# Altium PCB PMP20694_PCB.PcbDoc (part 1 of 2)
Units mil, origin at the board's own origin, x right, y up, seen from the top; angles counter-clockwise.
Board outline 7086.61 x 2677.17 mil, 2 copper layers (Top Layer, Bottom Layer), stack 62 mil thick; 190 components, 99 nets, 453 pads, 121 vias.
Unrouted connection lines stored in the file: 1.
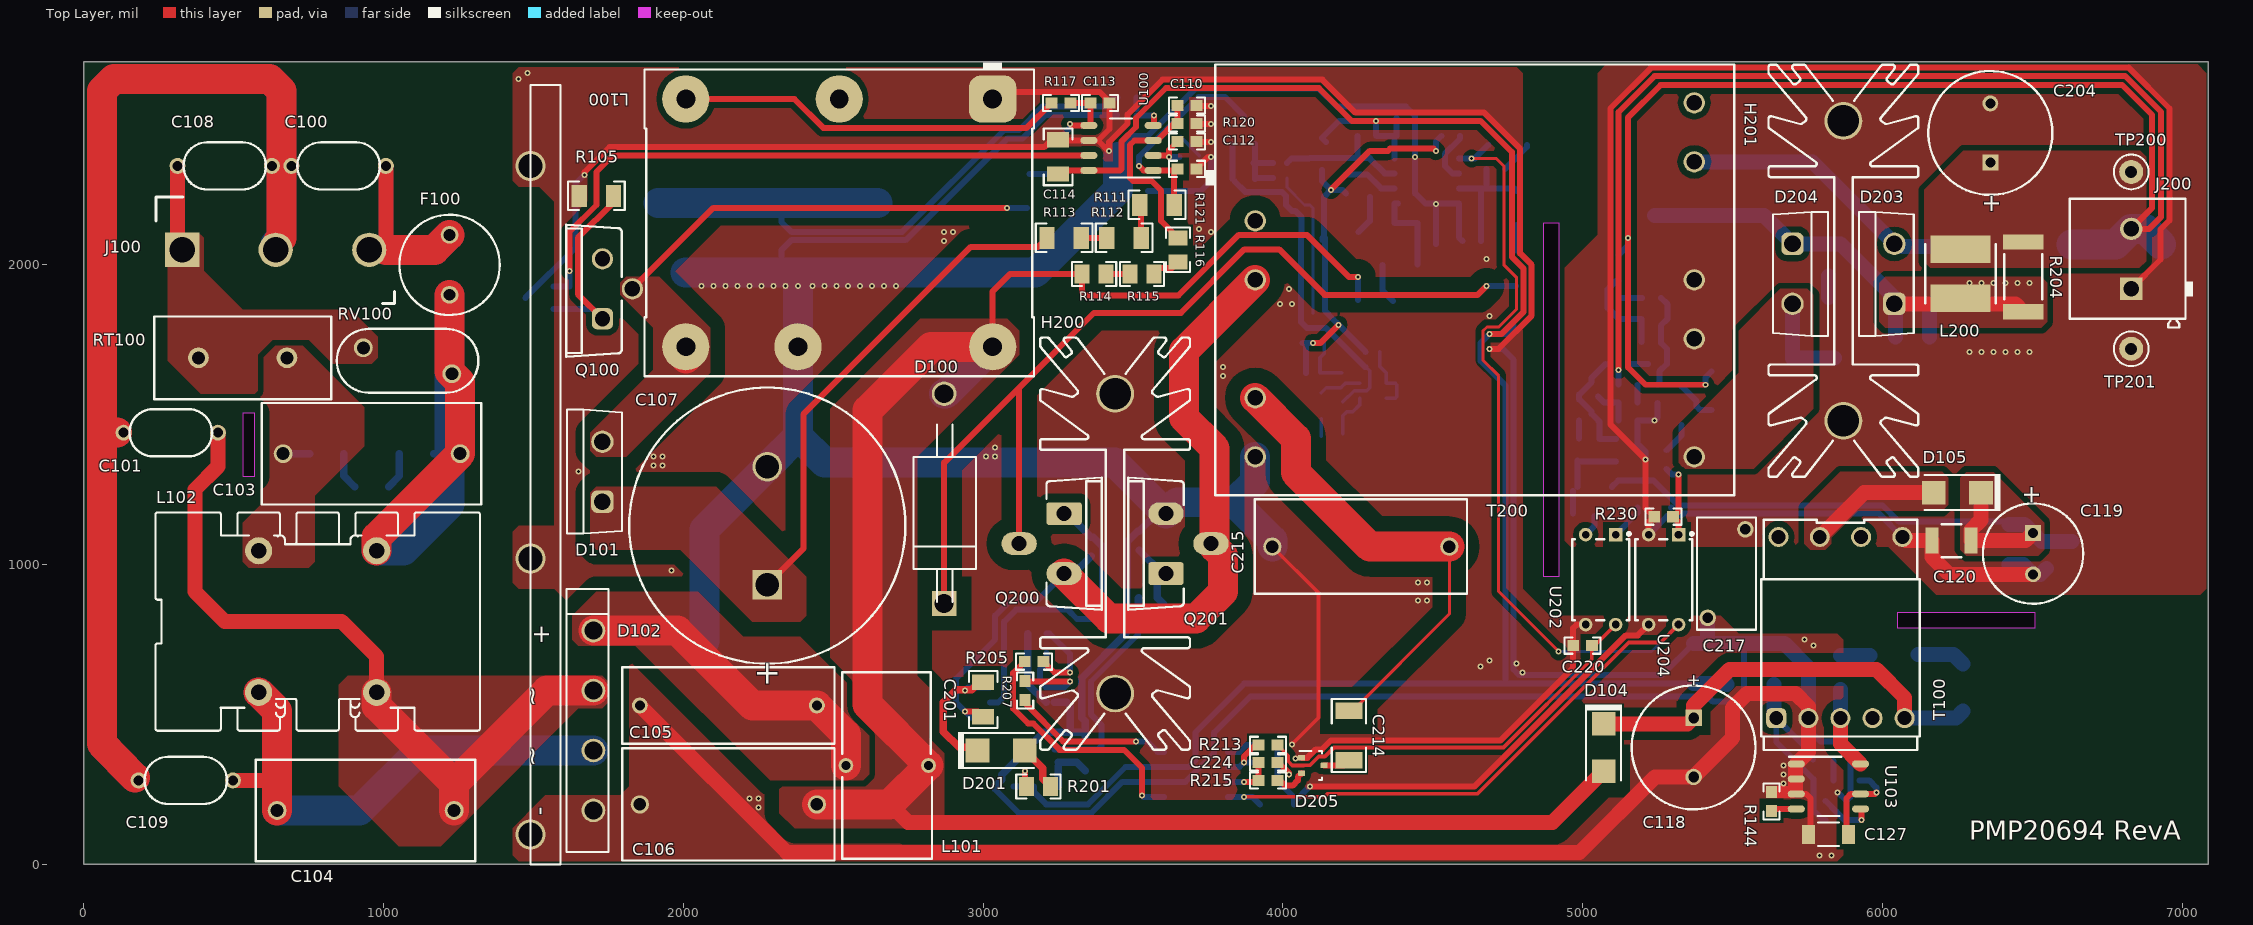
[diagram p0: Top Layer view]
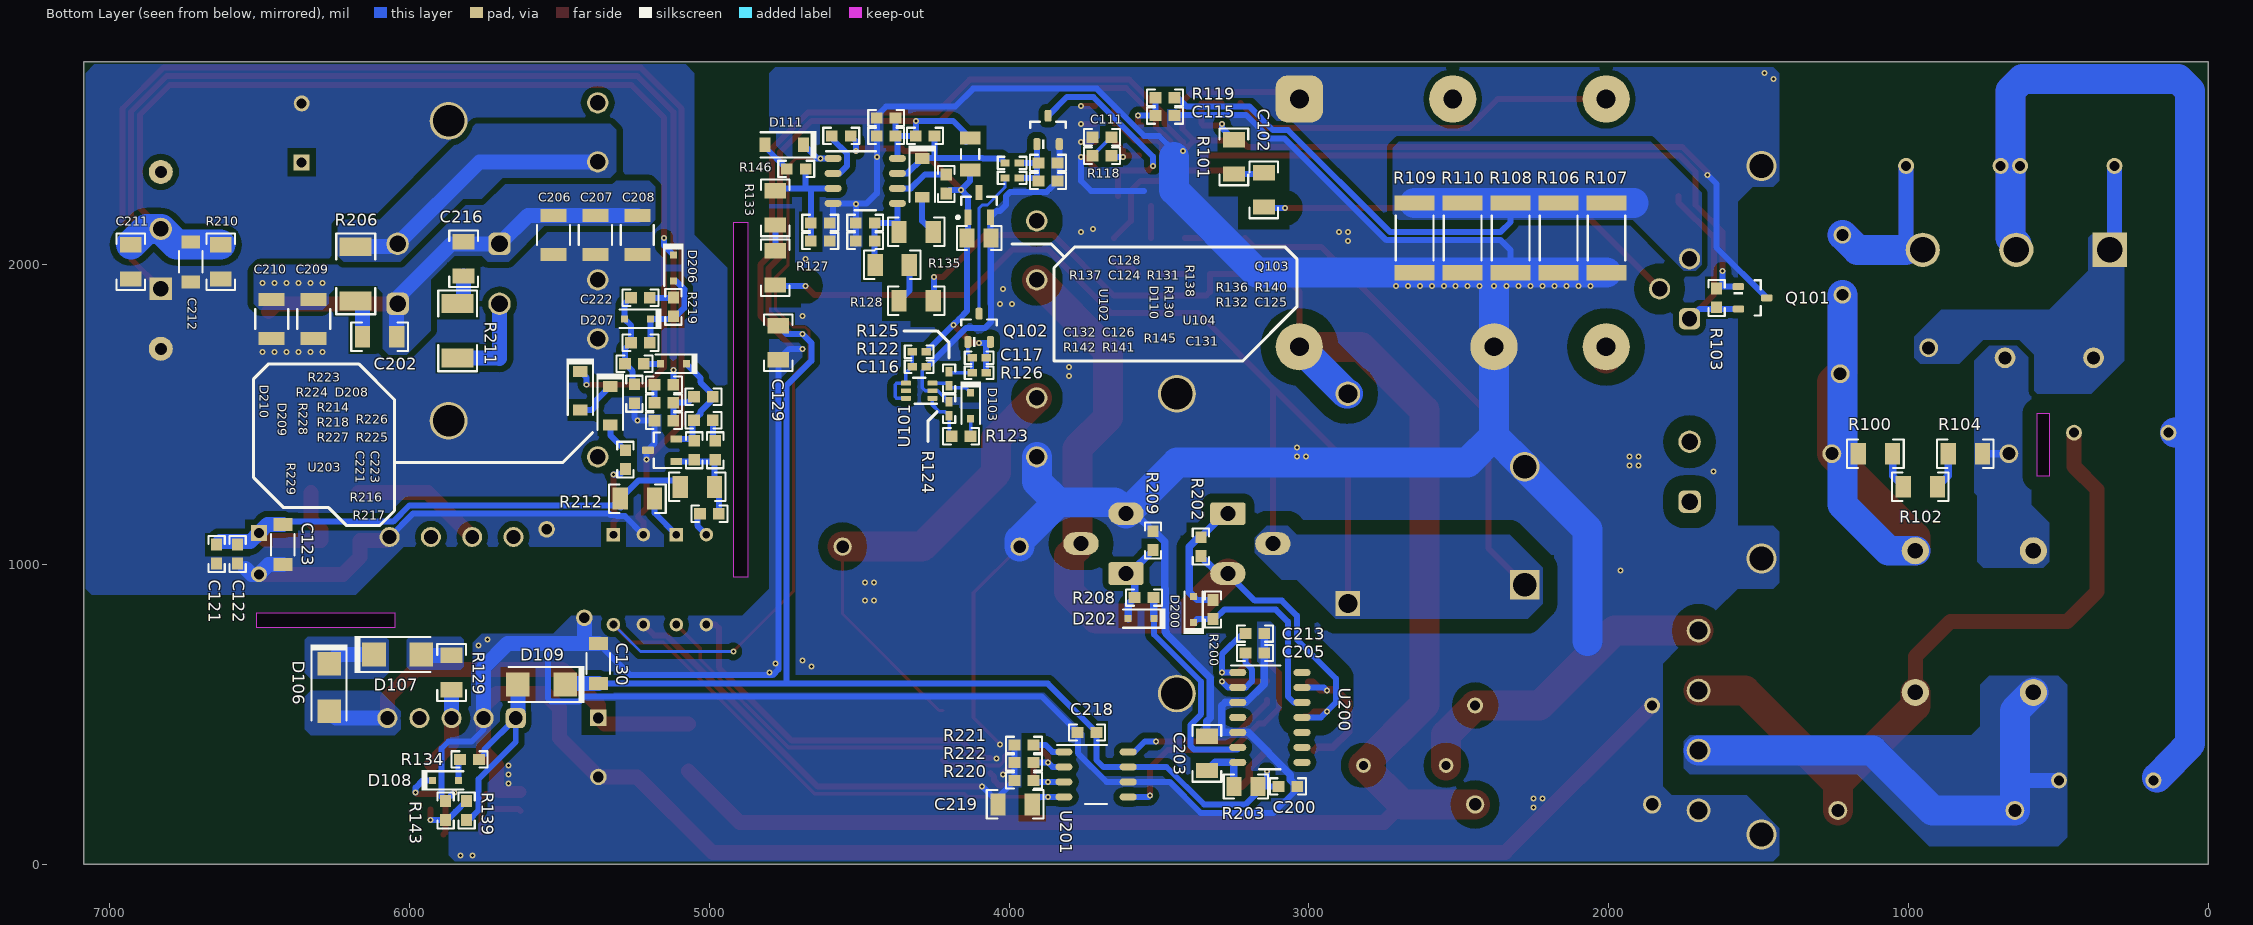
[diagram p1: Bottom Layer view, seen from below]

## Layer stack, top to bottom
Top Solder: solder mask 0.4, Solder Resist, Dk 3.5
Top Layer: signal copper 1.4
Dielectric1: core 59.2, FR-4, Dk 4.8
Bottom Layer: signal copper 1.4
Bottom Solder: solder mask 0.4, Solder Resist, Dk 3.5

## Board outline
0,0 7086.61,0 7086.61,2677.17 0,2677.17
cut-out: 530,1295 570,1295 570,1505 530,1505
cut-out: 6050,790 6510,790 6510,840 6050,840
cut-out: 4870,960 4870,2140 4920,2140 4920,960

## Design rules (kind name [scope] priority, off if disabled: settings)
AcuteAngle [All] p1: minimum=4.50000000000000E+0001 checktracksonly=FALSE
AssemblyTestPointUsage [All] p1: valid=2
Clearance Clearance_1 [InNetClass('HV') vs Not InNetClass('HV') and not InNetClass('MV')] p1: gap=50
Clearance Clearance_2 [InNetClass('MV') vs Not InNetClass('MV')] p2: gap=30
Clearance Clearance_Keepouts [((IsTrack Or IsArc) And Not InPoly) And IsFree and IsKeepOut vs ((IsTrack Or IsArc) And Not InPoly) And IsFree and IsKeepOut] p3: gap=0
Clearance Clearance_BoardEdge_MountingHoles [OnCopper and InComponentClass('Mounting Holes') vs IsKeepOut] p4: gap=40
Clearance Clearance_BoardEdge_Poly [OnCopper and InPoly vs IsKeepOut] p5: gap=25
Clearance Clearance_BoardEdge [OnCopper and Not InComponentClass('Logo') and not InComponentClass('FiducialMark') and not InRegion(1000,500,4000,800) and Not IsKeepout vs IsKeepOut] p6: gap=75
Clearance Clearance_Poly [InPolygon] p7: gap=20
Clearance [All] p8: gap=7.87
ComponentClearance ComponentClearance_MountingHoles_FiducialMarks [InComponentClass('Mounting Holes') vs InComponentClass('FiducialMark')] p1: gap=20 collisioncheckmode=3 verticalgap=10 showdistances=FALSE
ComponentClearance ComponentClearance_Shunt [InComponentClass('Header') vs InComponentClass('Shunt')] p2: gap=0 collisioncheckmode=3 verticalgap=0 showdistances=FALSE
ComponentClearance ComponentClearance_Logo [InComponentClass('Logo')] p3: gap=5 collisioncheckmode=3 verticalgap=10 showdistances=FALSE
ComponentClearance ComponentClearance_ScrewToNut [(HasFootprint('NY PMS 440 0025 PH')) vs (HasFootprint('Keystone_1902C'))] p4: gap=20 collisioncheckmode=3 verticalgap=100000 showdistances=FALSE
ComponentClearance ComponentClearance_MountingHoles [InComponentClass('Mounting Holes')] p5: gap=20 collisioncheckmode=3 verticalgap=10 showdistances=FALSE
ComponentClearance ComponentClearance_SmallPassives [HasFootprint('0201*') or HasFootprint('0402*') or HasFootprint('0508') or HasFootprint('0603*') or HasFootprint('0612') or HasFootprint('0805*') or HasFootprint('0815*') or HasFootprint('0830*') or HasFootprint('1206*') or HasFootprint('1210*') or HasFootprint('1808*') or HasFootprint('1812*') or HasFootprint('1825*') or HasFootprint('2010*') or HasFootprint('2220*') or HasFootprint('2225*') or HasFootprint('2512*') or HasFootprint('2728*') or HasFootprint('3518*') vs HasFootprint('0201*') or HasFootprint('0402*') or HasFootprint('0508') or HasFootprint('0603*') or HasFootprint('0612') or HasFootprint('0805*') or HasFootprint('0815*') or HasFootprint('0830*') or HasFootprint('1206*') or HasFootprint('1210*') or HasFootprint('1808*') or HasFootprint('1812*') or HasFootprint('1825*') or HasFootprint('2010*') or HasFootprint('2220*') or HasFootprint('2225*') or HasFootprint('2512*') or HasFootprint('2728*') or HasFootprint('3518*')] p6: gap=20 collisioncheckmode=3 verticalgap=20 showdistances=FALSE
ComponentClearance ComponentClearance_THtoSMT [IsThruComponent vs IsSMTComponent] p7: gap=10 collisioncheckmode=3 verticalgap=10 showdistances=FALSE
ComponentClearance ComponentClearance_THtoTH [IsThruComponent vs IsThruComponent] p8: gap=10 collisioncheckmode=3 verticalgap=10 showdistances=FALSE
ComponentClearance [All] p9: gap=10 collisioncheckmode=3 verticalgap=10 showdistances=FALSE
DiffPairsRouting [All] p1: maxlimit=100 minlimit=10 mostfreqgap=10 toplayer_minwidth=15 toplayer_maxwidth=15 toplayer_prefwidth=15 bottomlayer_minwidth=15 bottomlayer_maxwidth=15 bottomlayer_prefwidth=15 maxuncoupledlength=1000
FabricationTestPointUsage TestPointUsage [All] p1: valid=2 allowmultiple=FALSE
FabricationTestpoint Testpoint [All] p1: side=3 testpointundercomponent=TRUE minsize=40 maxsize=100 preferedsize=60 minholesize=0 maxholesize=40 preferedholesize=32 testpointgrid=1 allowsidetop=TRUE allowsidebottom=TRUE usegrid=TRUE gridtolerance=0.01
FanoutControl Fanout_LCC [IsLCC] p1: bgadir=Out bgaviamode=Centered fanoutstyle=Auto fanoutdirection=Alternating viagrid=1 // Fanout_LCC (Default Rule)
FanoutControl Fanout_BGA [IsBGA] p2: bgadir=Out bgaviamode=Centered fanoutstyle=Auto fanoutdirection=Alternating viagrid=1 // Fanout_BGA (Default Rule)
FanoutControl Fanout_Default [All] p4: bgadir=Out bgaviamode=Centered fanoutstyle=Auto fanoutdirection=Alternating viagrid=1 // Fanout_Default (Default Rule)
FanoutControl Fanout_Small [(CompPinCount < 5)] p5: bgadir=Out bgaviamode=Centered fanoutstyle=Auto fanoutdirection=OutThenIn viagrid=1 // Fanout_Small (Default Rule)
Height [All] p1: minheight=0 maxheight=3000 prefheight=500
HoleSize [All] p1: absolutevalues=TRUE maxlimit=251 minlimit=7 maxpercent=80.000 minpercent=20.000
MinimumAnnularRing MinimumAnnularRing_ThermalPadVias [IsVia and InAnyComponent] p1: minimumring=5.91
MinimumAnnularRing [All] p2: minimumring=4.9
MinimumSolderMaskSliver MinimumSolderMaskSliver_Logo [InComponentClass('Logo') vs InComponentClass('Logo')] p1: minsoldermaskwidth=0.7
MinimumSolderMaskSliver [All] p2: minsoldermaskwidth=2
PlaneConnect [All] p1: planeconnectstyle=Relief reliefexpansion=10 reliefentries=4 reliefconductorwidth=10 reliefairgap=10
PolygonConnect [All] p1: connectstyle=Direct reliefconductorwidth=10 reliefentries=4 polygonreliefangle="90 Angle" airgapwidth=10
PolygonConnect PolygonConnect_10 [All vs IsNamedPolygon('C108_1') Or  IsNamedPolygon('C103_2')] p2: connectstyle=Direct reliefconductorwidth=10 reliefentries=4 polygonreliefangle="90 Angle" airgapwidth=10
PolygonConnect PolygonConnect_9 [All vs IsNamedPolygon('C11_1') Or  IsNamedPolygon('Vin') Or  IsNamedPolygon('Vin') Or  IsNamedPolygon('5V') Or  IsNamedPolygon('D6_2') Or  IsNamedPolygon('Q3_3') Or  IsNamedPolygon('GND2') Or  IsNamedPolygon('GND2') Or  IsNamedPolygon('GND') Or  IsNamedPolygon('Q3_4') Or  IsNamedPolygon('12V5') Or  IsNamedPolygon('GND') Or  IsNamedPolygon('12V5') Or  IsNamedPolygon('D3_1')] p3: connectstyle=Direct reliefconductorwidth=10 reliefentries=4 polygonreliefangle="90 Angle" airgapwidth=10
PolygonConnect PolygonConnect_8 [All vs IsNamedPolygon('C11_1') Or  IsNamedPolygon('Vin') Or  IsNamedPolygon('12V5') Or  IsNamedPolygon('Q3_3') Or  IsNamedPolygon('GND2') Or  IsNamedPolygon('GND2') Or  IsNamedPolygon('5V') Or  IsNamedPolygon('Q3_4') Or  IsNamedPolygon('12V5')] p4: connectstyle=Direct reliefconductorwidth=10 reliefentries=4 polygonreliefangle="90 Angle" airgapwidth=10
PolygonConnect PolygonConnect_7 [All vs IsNamedPolygon('GND2') Or  IsNamedPolygon('GND2') Or  IsNamedPolygon('5V') Or  IsNamedPolygon('12V5') Or  IsNamedPolygon('12V5') Or  IsNamedPolygon('C11_1')] p5: connectstyle=Direct reliefconductorwidth=10 reliefentries=4 polygonreliefangle="90 Angle" airgapwidth=10
PolygonConnect PolygonConnect_6 [All vs IsNamedPolygon('GND2') Or  IsNamedPolygon('SGND') Or  IsNamedPolygon('GND1') Or  IsNamedPolygon('C901_1') Or  IsNamedPolygon('SGND') Or  IsNamedPolygon('GND2') Or  IsNamedPolygon('GND1')] p6: connectstyle=Direct reliefconductorwidth=10 reliefentries=4 polygonreliefangle="90 Angle" airgapwidth=10
PolygonConnect PolygonConnect_5 [All vs IsNamedPolygon('GND1') Or  IsNamedPolygon('GND1')] p7: connectstyle=Direct reliefconductorwidth=10 reliefentries=4 polygonreliefangle="90 Angle" airgapwidth=10
PolygonConnect PolygonConnect_4 [All vs IsNamedPolygon('C21_1') Or  IsNamedPolygon('C5_1') Or  IsNamedPolygon('C12_2') Or  IsNamedPolygon('C2_2') Or  IsNamedPolygon('C13_1') Or  IsNamedPolygon('C28_1') Or  IsNamedPolygon('C6_1') Or  IsNamedPolygon('GND') Or  IsNamedPolygon('GND2') Or  IsNamedPolygon('C14_1') Or  IsNamedPolygon('C13_1') Or  IsNamedPolygon('Q1_3') Or  IsNamedPolygon('C14_1') Or  IsNamedPolygon('C5_1') Or  IsNamedPolygon('GND2') Or  IsNamedPolygon('C28_1') Or  IsNamedPolygon('D5_2') Or  IsNamedPolygon('D6_2') Or  IsNamedPolygon('D2_1') Or  IsNamedPolygon('C12_2') Or  IsNamedPolygon('D2_1') Or  IsNamedPolygon('C4_1') Or  IsNamedPolygon('C4_1') Or  IsNamedPolygon('C2_2') Or  IsNamedPolygon('GND') Or  IsNamedPolygon('C33_1') Or  IsNamedPolygon('C9_1')] p8: connectstyle=Direct reliefconductorwidth=10 reliefentries=4 polygonreliefangle="90 Angle" airgapwidth=10
PolygonConnect PolygonConnect_3 [All vs IsNamedPolygon('C28_1') Or  IsNamedPolygon('C12_2') Or  IsNamedPolygon('C28_1') Or  IsNamedPolygon('C9_1') Or  IsNamedPolygon('D5_2') Or  IsNamedPolygon('C12_2') Or  IsNamedPolygon('C2_2') Or  IsNamedPolygon('C14_1') Or  IsNamedPolygon('C4_1') Or  IsNamedPolygon('C14_1') Or  IsNamedPolygon('D6_2') Or  IsNamedPolygon('GND2') Or  IsNamedPolygon('Q1_3') Or  IsNamedPolygon('C5_1') Or  IsNamedPolygon('D2_1') Or  IsNamedPolygon('C4_1') Or  IsNamedPolygon('C13_1') Or  IsNamedPolygon('C5_1') Or  IsNamedPolygon('C13_1') Or  IsNamedPolygon('C33_1') Or  IsNamedPolygon('D2_1') Or  IsNamedPolygon('GND') Or  IsNamedPolygon('GND') Or  IsNamedPolygon('GND2') Or  IsNamedPolygon('C2_2') Or  IsNamedPolygon('C6_1') Or  IsNamedPolygon('C21_1')] p9: connectstyle=Direct reliefconductorwidth=10 reliefentries=4 polygonreliefangle="90 Angle" airgapwidth=10
PolygonConnect PolygonConnect_2 [All vs IsNamedPolygon('C21_1') Or  IsNamedPolygon('C4_1') Or  IsNamedPolygon('D5_2') Or  IsNamedPolygon('C5_1') Or  IsNamedPolygon('C14_1') Or  IsNamedPolygon('C13_1') Or  IsNamedPolygon('C4_1') Or  IsNamedPolygon('C33_1') Or  IsNamedPolygon('C12_2') Or  IsNamedPolygon('D2_1') Or  IsNamedPolygon('C2_2') Or  IsNamedPolygon('C28_1') Or  IsNamedPolygon('C12_2') Or  IsNamedPolygon('D2_1') Or  IsNamedPolygon('C5_1') Or  IsNamedPolygon('Q1_3') Or  IsNamedPolygon('GND') Or  IsNamedPolygon('D6_2') Or  IsNamedPolygon('C6_1') Or  IsNamedPolygon('C2_2') Or  IsNamedPolygon('C14_1') Or  IsNamedPolygon('C28_1') Or  IsNamedPolygon('C13_1') Or  IsNamedPolygon('C9_1') Or  IsNamedPolygon('GND')] p10: connectstyle=Direct reliefconductorwidth=10 reliefentries=4 polygonreliefangle="90 Angle" airgapwidth=10
PolygonConnect PolygonConnect_1 [All vs IsNamedPolygon('C28_1') Or  IsNamedPolygon('D5_2') Or  IsNamedPolygon('C5_1') Or  IsNamedPolygon('C5_1') Or  IsNamedPolygon('D2_1') Or  IsNamedPolygon('C21_1') Or  IsNamedPolygon('C9_1') Or  IsNamedPolygon('C4_1') Or  IsNamedPolygon('C14_1') Or  IsNamedPolygon('C28_1') Or  IsNamedPolygon('C6_1') Or  IsNamedPolygon('C12_2') Or  IsNamedPolygon('C33_1') Or  IsNamedPolygon('C4_1') Or  IsNamedPolygon('C13_1') Or  IsNamedPolygon('C12_2') Or  IsNamedPolygon('D6_2') Or  IsNamedPolygon('C2_2') Or  IsNamedPolygon('C14_1') Or  IsNamedPolygon('D2_1') Or  IsNamedPolygon('C2_2') Or  IsNamedPolygon('C13_1')] p11: connectstyle=Direct reliefconductorwidth=10 reliefentries=4 polygonreliefangle="90 Angle" airgapwidth=10
RoutingVias ThermalPadVias [IsVia and InAnyComponent] p1: holewidth=7.87 width=19.68 viastyle="Through Hole" minholewidth=7.87 minwidth=19.68 maxholewidth=12.99 maxwidth=23.62
RoutingVias [All] p2: holewidth=16 width=34 viastyle="Through Hole" minholewidth=7.87 minwidth=20 maxholewidth=40 maxwidth=65
SilkToBoardRegionClearance [Not ((IsComment or IsDesignator) And (Hide <> 'False')) and not InRegion(1000,500,4000,800)] p1:
SilkToSilkClearance SilkToSilkClearance_Pb-FreeLogo [(HasFootprint('Pb-Free_Overlay_Medium') OR HasFootprint('Pb-Free_Overlay_Small')) vs (HasFootprint('Pb-Free_Overlay_Medium') OR HasFootprint('Pb-Free_Overlay_Small'))] p1: silktosilkclearance=0
SilkToSilkClearance [All] p2: silktosilkclearance=1
SilkToSolderMaskClearance "Silk to Solder Mask Opening" [All] p1: minsilkscreentomaskgap=1 clearancetoexposedcopper=FALSE
SolderMaskExpansion [All] p1: expansion=1.97
Width [All] p1: maxlimit=100 minlimit=6 preferedwidth=10 checkconnectedcopper=TRUE
14 further rules are at their usual default settings.

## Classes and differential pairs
component class PMP20694_BlankSheet: C2 C12 C13 C20 C200 C201 C202 C203 C204 C205 C206 C207 C208 C209 C210 C211 C212 C213 C214 C215 C216 C217 C218 C219 C220 C221 C222 C223 C224 D200 D201 D202 D203 D204 D205 D206 D207 D208 D209 D210 H200 H201 J200 L200 Q200 Q201 R200 R201 R202 R203 R204 R205 R206 R207 R208 R209 R210 R211 R212 R213 R214 R215 R216 R217 R218 R219 R220 R221 R222 R223 R224 R225 R226 R227 R228 R229 R230 T200 TP200 TP201 U1 U200 U201 U202 U203 U204
net class HV: B+ NetC100_2 NetC101_2 NetC102_1 NetC102_2 NetC103_1 NetC103_2 NetC104_2 NetC105_1 NetC108_1 NetC201_2 NetC214_1 VREC
net class MV: NetC118_1 NetC201_1 NetD106_1 NetD107_2 NetD200_1 NetD200_2 NetR111_1 NetR112_1 NetR114_1 NetR115_1 NetR127_1 NetR128_1 NetR129_2

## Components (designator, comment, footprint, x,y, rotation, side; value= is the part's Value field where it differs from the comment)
C100 "DE2B3KY101KN3AU02F" CAPRD500W60D700H850 850,2330 r0 top
C101 "DE2B3KY221KN3AU02F" CAPRD500W60D700H850 290,1440 r0 top
C102 "GRM31A7U3A470JW31D" 1206 3150,2250 r90 bottom
C103 "890334025039CS" WCAP-FTXX_P15xPL4 960,1370 r180 top
C104 "890334025039CS" WCAP-FTXX_P15xPL4 940,180 r180 top
C105 "450MPK474J" MPK_1800x650 2150,530 r180 top
C106 "450MPK105J" MPK_1800x950 2150,200 r180 top
C107 "500MXG150MEFCSN22X55" SLPX_A5 2280,1130 r90 top
C108 "DE2B3KY101KN3AU02F" CAPRD500W60D700H850 470,2330 r0 top
C109 "DE2B3KY221KN3AU02F" CAPRD500W60D700H850 340,280 r180 top
C110 "06035A102KAT2A" 0603 3680,2531.46 r0 top
C111 "885012206048" 0603 3690,2425.67 r0 bottom
C112 "C0603C105K8PACTU" 0603 3680,2411.46 r0 top
C113 "06035A180JAT2A" 0603 3390,2540 r0 top
C114 "12065C224KAT2A" 1206 3250,2360 r90 top
C115 "06035A221FAT2A" 0603 3480,2497.76 r180 bottom
C116 "GRM155R61C104KA88D" 0402 4300,1660 r180 bottom
C117 "GRM155R61C104KA88D" 0402 4100,1690 r0 bottom
C118 "B43888G5685M000" B43888_1000x2000 5370,390 r270 top
C119 "EEU-FM1E221" CAPPRD350W60D800H1150 6502.62,1036.65 r270 top
C120 "12103D226MAT2A" 1210_280 6230,1080 r0 top
C121 "06033C104JAT2A" 0603 6643.92,1035.16 r270 bottom
C122 "06033C104JAT2A" 0603 6573.92,1035.16 r270 bottom
C123 "CGA5L3X7R1H105K160AB" 1206_180 6422.62,1066.65 r270 bottom
C124 "06033D104KAT2A" 0603 4410,2430 r0 bottom
C125 "06033C104JAT2A" 0603 3870,2280 r180 bottom
C126 "C0603C225K8PACTU" 0603 4480,2140 r0 bottom
C127 "GRM31CR61E106KA12L" 1206_180 5820,100 r0 top
C128 "06033C104JAT2A" 0603 4410,2490 r0 bottom
C129 "GRM31MR71H105KA88L" 1206 4770,1740 r270 bottom
C130 "1206YD226MAT2A" 1206_190 5370,670 r90 bottom
C131 "08051A102JAT2A" 0805_HV 4100,2090 r180 bottom
C132 "C0603C682J5RACTU" 0603 4630,2140 r180 bottom
C200 "UMK107AB7105KA-T" 0603 3070,260 r0 bottom
C201 "12065C104KAT2A" 1206 3000,550 r270 top
C202 "Used in BOM report" 1206 6100,1760 r0 bottom
C203 "12063C105KAT2A" 1206 3340,370 r90 bottom
C204 "ELXZ500ELL331MJ25S" Chemi-Con_1000x2500 6360,2440 r90 top
C205 "06035A101FAT2A" 0603 3180,705 r180 bottom
C206 "C3225X5R1H335K250AB" 1210_280 5520,2100 r90 bottom
C207 "C3225X5R1H335K250AB" 1210_280 5380,2100 r90 bottom
C208 "C3225X5R1H335K250AB" 1210_280 5240,2100 r90 bottom
C209 "C3225X5R1H335K250AB" 1210_280 6320,1820 r90 bottom
C210 "C3225X5R1H335K250AB" 1210_280 6460,1820 r90 bottom
C211 "12065C104KAT2A" 1206 6930,2010 r270 bottom
C212 "CGA5L3X7R1H105K160AB" 1206_180 6730,2010 r270 bottom
C213 "06035A101FAT2A" 0603 3180,770 r0 bottom
C214 "VJ1808Y101KXEAT5Z" 1808 4220,430 r270 top
C215 "121MPE223J" CAPRR1500W80L1800T800H1550 4260,1060 r180 top
C216 "Used in BOM report" 1206 5820,2020 r270 bottom
C217 "AY2222M35Y5US63L7" AY2_950x500_Straight 5480,970 r270 top
C218 "06033C104JAT2A" 0603 3740,440 r0 bottom
C219 "12063C474KAT2A" 1206 3980,200 r0 bottom
C220 "06031C103JAT2A" 0603 5000,730 r180 top
C221 "06033C101KAT2A" 0603 5050,1381.5 r270 bottom
C222 "C0603C105K4PACTU" 0603 5230,1890 r0 bottom
C223 "GRM188R61H103KA01D" 0603 4980,1381.5 r270 bottom
C224 "C0603C105K4PACTU" 0603 3950,340 r0 top
D100 "1N5406" DO-201AD 2870,1170 r90 top
D101 "MUR860G" TO-220AC 1730,1310 r90 top
D102 "GBU6J-BP" GBU 1700,480 r270 top
D103 "BAT42WS" sod-323 4128.19,1530 r270 bottom
D104 "US1M-13-F" SMA 5070,390 r270 top
D105 "SS1150-LTP" SMA 6250,1240 r180 top
D106 "SMAJ120A" SMA 6268.5,590 r270 bottom
D107 "US1M-13-F" SMA 6040,700 r180 bottom
D108 "BAS20HT1G" sod-323 5880,280 r180 bottom
D109 "SS110-TP" SMA 5560,600 r0 bottom
D110 "BAV21W-7-F" SOD-123 4290,2290 r270 bottom
D111 "BAV21W-7-F" SOD-123 4750,2400 r0 bottom
D200 "NF" sod-323 3384.48,850 r90 bottom
D201 "MURA160T3G" SMA 3060,380 r0 top
D202 "NF" sod-323 3560,820 r0 bottom
D203 "STPS20120D" TO-220AC 6040,1970 r90 top
D204 "STPS20120D" TO-220AC 5700,1970 r270 top
D205 "BAV99WT1G" SOT-323 4100,330 r0 top
D206 "MMSZ5242BS-7-F" SOD-323 5120,1990 r270 bottom
D207 "BAT54HT1G" sod-323 5240,1820 r0 bottom
D208 "BAS316,115" sod-323 5120,1670 r0 bottom
D209 "20V" SOD-123 5330,1530 r270 bottom
D210 "20V" SOD-123 5430,1580 r270 bottom
F100 "37213150001" FUSE_372 1220,2000 r90 top
H200 "513102B02500G" Aavid_513102B02500G 3440,1070 r270 top
H201 "513102B02500G" Aavid_513102B02500G 5870,1980 r90 top
J100 "1-1318301-3" TE_1-1318301-3 640,2050 r0 top
J200 "1715721" PhoenixContact_1715721 6830,2020 r90 top
L100 "PFC3125ER-231K06B-00" TDK_PFC3125ER 2520,2140 r270 top
L101 "7447076" IND_7447020 2680,330 r0 top
L102 "744824310" IND_WE-CMB_L 780,810 r0 top
L200 "SRN6045TA-1R0Y" SRN6045TA 6260,1970 r90 top
Q100 "IPA65R190C7XKSA1" TO-220AB_100mil 1730,1920 r90 top
Q101 "MMBT4403" SOT-23 1520,1890 r180 bottom
Q102 "MMBT4403" SOT-23 4100,1790 r90 bottom
Q103 "2N7002" SOT-23 3870,2450 r90 bottom
Q200 "IPP65R310CFD" TO-220AB 3270,1070 r270 top
Q201 "IPP65R310CFD" TO-220AB 3610,1070 r90 top
R100 "CRCW1206750KFKEA" 1206 1110,1370 r0 bottom
R101 "CRCW120622K0JNEA" 1206 3250,2360 r270 bottom
R102 "CRCW1206301KFKEA" 1206 960,1260 r0 bottom
R103 "CRCW06033R00JNEA" 0603 1640,1890 r270 bottom
R104 "CRCW1206750KFKEA" 1206 810,1370 r0 bottom
R105 "CRCW120610K0FKEA" 1206 1710,2230 r0 top
R106 "ERJ-1TRQFR68U" 2512 2167.01,2090 r90 bottom
R107 "ERJ-1TRQFR68U" 2512 2007.01,2090 r90 bottom
R108 "ERJ-1TRQFR68U" 2512 2327.01,2090 r90 bottom
R109 "ERJ-1TRQFR68U" 2512 2647.01,2090 r90 bottom
R110 "ERJ-1TRQFR68U" 2512 2487.01,2090 r90 bottom
R111 "CRCW1206511KFKEA" 1206 3580,2200 r0 top
R112 "CRCW1206511KFKEA" 1206 3470,2090 r0 top
R113 "CRCW1206511KFKEA" 1206 3270,2090 r0 top
R114 "CRCW0805560KJNEA" 0805_HV 3370,1970 r180 top
R115 "CRCW0805560KJNEA" 0805_HV 3530,1970 r180 top
R116 "CRCW0805560KJNEA" 0805_HV 3650,2050 r270 top
R117 "CRCW060343K2FKEA" 0603 3260,2540 r0 top
R118 "CRCW060310K0JNEA" 0603 3690,2364.21 r180 bottom
R119 "CRCW06031K00JNEA" 0603 3480,2557.76 r180 bottom
R120 "CRCW060310K0FKEA" 0603 3680,2471.46 r180 top
R121 "CRCW06038K66FKEA" 0603 3680,2320 r180 top
R122 "ERJ-2GE0R00X" 0402 4300,1710 r180 bottom
R123 "CRCW06032M20JNEA" 0603 4160,1428.03 r0 bottom
R124 "CRCW0402619KFKED" 0402 4200,1520 r270 bottom
R125 "CRCW040210K0FKED" 0402 4200,1620 r270 bottom
R126 "CRCW040210K0FKED" 0402 4100,1640 r180 bottom
R127 "CRCW1206499KFKEA" 1206 4780,1990 r270 bottom
R128 "CRCW12061M00JNEA" 1206 4310,1880 r180 bottom
R129 "CRCW12060000Z0EA" 1206 5860,640 r270 bottom
R130 "CRCW06031K00FKEA" 0603 4210,2270 r270 bottom
R131 "CRCW060312K0JNEA" 0603 4280,2430 r0 bottom
R132 "CRCW0402100RFKED" 0402 3990,2290 r0 bottom
R133 "CRCW1206499KFKEA" 1206 4780,2190 r270 bottom
R134 "CRCW060315R0FKEA" 0603 5800,350 r0 bottom
R135 "CRCW12061M00JNEA" 1206 4390,2000 r180 bottom
R136 "CRCW0402100RFKED" 0402 3990,2340 r180 bottom
R137 "CRCW06031K00FKEA" 0603 4560,2430 r180 bottom
R138 "ERJ-8ENF2001V" 1206L 4130,2370 r90 bottom
R139 "CRCW060348K7FKEA" 0603 5810,180 r270 bottom
R140 "CRCW0603100KFKEA" 0603 3870,2340 r0 bottom
R141 "CRCW060323K7FKEA" 0603 4480,2080 r180 bottom
R142 "CRCW060316K2FKEA" 0603 4630,2080 r0 bottom
R143 "CRCW060320K5FKEA" 0603 5880,180 r270 bottom
R144 "CRCW06032K05FKEA" 0603 5630,210 r270 top
R145 "CRCW12061M00JNEA" 1206 4310,2110 r0 bottom
R146 "CRCW060341K2FKEA" 0603 4710,2320 r0 bottom
R200 "CRCW060310R0FKEA" 0603 3320,850 r90 bottom
R201 "CRCW08052R20JNEA" 0805_HV 3184.41,260 r0 top
R202 "CRCW060310K0FKEA" 0603 3360,1060 r90 bottom
R203 "ERJ-6RQF1R0V" 0805_HV 3210,260 r180 bottom
R204 "CSR2512FGR500" 2512 6470,1960 r90 top
R205 "CRCW060351R1FKEA" 0603 3170,676.46 r180 top
R206 "Used in BOM report" 2010 6180,1970 r90 bottom
R207 "CRCW060351R1FKEA" 0603 3140,580 r270 top
R208 "CRCW060310R0FKEA" 0603 3550,890 r0 bottom
R209 "CRCW060310K0FKEA" 0603 3520,1080 r90 bottom
R210 "CRCW120610K0FKEA" 1206 6630,2010 r90 bottom
R211 "Used in BOM report" 2010 5840,1780 r270 bottom
R212 "CRCW12064K99FKEA" 1206 5240,1220 r0 bottom
R213 "CRCW06031K47FKEA" 0603 3950,398.54 r0 top
R214 "CRCW0603332RFKEA" 0603 5151.81,1600 r180 bottom
R215 "CRCW06030000Z0EA" 0603 3950,280 r0 top
R216 "CRCW120610K0FKEA" 1206 5040,1259.37 r0 bottom
R217 "CRCW060315R0FKEA" 0603 5000,1170 r180 bottom
R218 "CRCW060333K2FKEA" 0603 5151.81,1540 r0 bottom
R219 "CRCW06030000Z0EA" 0603 5120,1860 r270 bottom
R220 "RC0603FR-07100RL" 0603 3950,280 r180 bottom
R221 "CRCW060320K0FKEA" 0603 3950,398.54 r180 bottom
R222 "CRCW06034K12FKEA" 0603 3950,340 r180 bottom
R223 "CRCW06031M00JNEA" 0603 5230,1740 r180 bottom
R224 "CRCW06032K00JNEA" 0603 5250,1670 r0 bottom
R225 "CRCW060310K0FKEA" 0603 5020,1481.5 r0 bottom
R226 "CRCW06030000Z0EA" 0603 5020,1560 r0 bottom
R227 "CRCW06032K49FKEA" 0603 5151.81,1480 r180 bottom
R228 "CRCW060351K1FKEA" 0603 5250,1570 r90 bottom
R229 "RC0603FR-072KL" 0603 5280,1350 r90 bottom
R230 "CRCW06031K00FKEA" 0603 5270,1160 r0 top
RT100 "B57237S229M" S237 530,1690 r0 top
RV100 "S10K275E2" VAR_S10K275E2 1080,1680 r0 top
T100 "750316711" Wurth_EE13-7-4_5662 5860,790 r90 top
T200 "750316706" Wurth_ERL35_5783_D125912 4640,1950 r0 top
TP200 "5000" Keystone5000 6830,2310 r0 top
TP201 "5001" Keystone5001 6830,1720 r0 top
U100 "UCC28051DR" D0008A_N 3460,2390 r180 top
U101 "TMP300BIDCKR" DCK0006A_N 4300,1580 r0 bottom
U102 "LM393D" D0008A_N 4480,2280 r180 bottom
U103 "UCC28910DR" D0007A_N 5820,260 r0 top
U104 "LM4040CIM3-5.0" MF03A_N 4100,2200 r90 bottom
U200 "UCC27714D" D0014A_N 3130,490 r180 bottom
U201 "UCC25600D" D0008A_N 3710,300 r180 bottom
U202 "FOD817D300" DIP-4 5060,950 r270 top
U203 "TL431AIDBZR" DBZ0003A_N 5157.81,1381.5 r0 bottom
U204 "FOD817D300" DIP-4 5270,950 r270 top

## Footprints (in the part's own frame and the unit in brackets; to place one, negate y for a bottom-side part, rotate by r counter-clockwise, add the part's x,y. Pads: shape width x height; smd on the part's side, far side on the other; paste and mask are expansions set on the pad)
0402 [mm] "0402 from SM-752 data"
  rect 0.8x0.6 smd: 1(-0.6,0) 2(0.6,0)
  silkscreen extent -1.22,-0.52 1.22,0.52, body extent -0.55,-0.3 0.55,0.3, height 0.6
0603 [mm] "0603 from SM-752 data"
  rect 1x0.95 smd: 1(-0.8,0) 2(0.8,0)
  silkscreen extent -1.52,-0.69 1.52,0.69, body extent -0.87,-0.47 0.87,0.47, height 1
0805_HV [mil] "0805 with 30mil clearance between pads"
  rect 50x63 smd: 1(-40,0) 2(40,0)
  silkscreen extent -74,-40 74,40, body extent -43,-29 43,29, height 57
1206 [mm] "1206 from SM-752 data"
  rect 1.3x1.85 smd: 1(-1.45,0) 2(1.45,0)
  silkscreen extent -2.4,-1.21 2.4,1.21, body extent -1.7,-0.9 1.7,0.9, height 1.35
1206_180 [mm] "1206_180"
  rect 1.1x1.6 smd: 1(-1.7,0) 2(1.7,0)
  silkscreen extent -0.9,-1 0.9,1, body extent -1.75,-0.95 1.75,0.95, height 1.8
1206_190 [mm] "1206_190"
  rect 1.1x1.6 smd: 1(-1.7,0) 2(1.7,0)
  silkscreen extent -0.9,-1 0.9,1, body extent -1.75,-0.95 1.75,0.95, height 1.9
1206L [mm] "1206 from SM-752 data"
  rect 1.1x1.75 smd: 1(-1.35,0) 2(1.35,0)
  silkscreen extent -0.4,-0.77 0.4,0.77, body extent -1.7,-0.9 1.7,0.9, height 1.35
1210_280 [mm] "SMD, 2-Leads, Body 3.6x2.8mm, Height 2.8mm"
  rect 1.1x2.2 smd: 1(-1.65,0) 2(1.65,0)
  silkscreen extent -0.84,-1.4 0.84,1.4, body extent -1.8,-1.4 1.8,1.4, height 2.8
1808 [mm] "Chip Capacitor, Body 4.6x2.0mm, IPC Medium Density"
  rect 1.4x2.3 smd: 1(-2.1,0) 2(2.1,0)
  silkscreen extent -3.1,-1.45 3.1,1.45, body extent -2.47,-1.2 2.47,1.2, height 2.03
2010 [mm] "Chip Capacitor, Body 5.08x2.54mm, IPC Medium Density"
  rect 1.6x2.7 smd: 1(-2.3,0) 2(2.3,0)
  silkscreen extent -3.42,-1.65 3.42,1.65, body extent -2.73,-1.45 2.73,1.45, height 1.66
2512 [mm] "Chip Resistor, Body 6.3x3.2mm, IPC Medium Density"
  rect 1.3x3.4 smd: 1(-2.95,0) 2(2.95,0)
  silkscreen extent -1.9,-1.6 1.9,1.6, body extent -3.22,-1.67 3.22,1.67, height 0.71
Aavid_513102B02500G [mm] "Heat Sink TO-220 Aluminum"
  round 3.2 hole 2.67: 1(-12.7,0) 2(12.7,0)
  silkscreen extent -17.46,-6.35 17.46,6.35, body extent -17.5,-6.3 17.42,6.4, height 38.1
AY2_950x500_Straight [mm] "TH, 2-Leads, 9.5x5mm, Pin Spacing 7.5mm"
  round 1.4 hole 0.9: 1(-3.75,1.6) 2(3.75,-1.6)
  silkscreen extent -4.75,-2.5 4.75,2.5, body extent -4.74,-2.5 4.75,2.5, height 12.5
B43888_1000x2000 [mm] "TH, 2-Leads, Dia 10mm, Pin Spacing 5mm"
  rect 1.4x1.4 hole 0.9: 1(-2.5,0)
  round 1.4 hole 0.9: 2(2.5,0)
  silkscreen extent -5.25,-5.25 5.25,5.25, body extent -5.21,-5.24 5.24,5.24, height 22.01
CAPPRD350W60D800H1150 [mm] "Based on Nichicon L8 series"
  rect 1.35x1.35 hole 0.85: 1(-1.75,0)
  round 1.35 hole 0.85: 2(1.75,0)
  silkscreen extent -4.25,-4.25 4.25,4.25, body extent -4.22,-4.24 4.24,4.24, height 13.51
CAPRD500W60D700H850 [mm] "RADIAL CAPACITOR"
  round 1.35 hole 0.85: 1(-4,0) 2(4,0)
  silkscreen extent -3.5,-2 3.5,2, body extent -3.47,-2.5 3.5,2.5, height 9.99
CAPRR1500W80L1800T800H1550 [mm] "RUBYCON"
  round 1.55 hole 1.05: 1(-7.5,0) 2(7.5,0)
  silkscreen extent -9,-4 9,4, body extent -9,-4 9,4, height 16.5
Chemi-Con_1000x2500 [mm] "TH, 2-Leads, Dia 10mm, Lead Spacing 5mm"
  rect 1.35x1.35 hole 0.85: 1(-2.5,0)
  round 1.35 hole 0.85: 2(2.5,0)
  silkscreen extent -5.25,-5.25 5.25,5.25, body extent -5.25,-5.25 5.26,5.25, height 26.51
D0007A_N [mm] "SOIC, 7-Leads, Body 4.9x3.9mm, Pitch 1.27mm, IPC Medium Density"
  oval 1.45x0.6 smd: 1(-2.725,1.905) 2(-2.725,0.635) 3(-2.725,-0.635) 4(-2.725,-1.905) 5(2.725,-1.905) 6(2.725,-0.635) 8(2.725,1.905)
  silkscreen extent -3.32,-2.5 1.1,2.52, body extent -3.01,-2.45 3.01,2.45, height 1.75
D0008A_N [mm] "SOIC, 8-Leads, Body 4.9x3.9mm, Pitch 1.27mm, IPC Medium Density"
  oval 1.45x0.6 smd: 1(-2.725,1.905) 2(-2.725,0.635) 3(-2.725,-0.635) 4(-2.725,-1.905) 5(2.725,-1.905) 6(2.725,-0.635) 7(2.725,0.635) 8(2.725,1.905)
  silkscreen extent -3.3,-2.5 0.9,2.5, body extent -3,-2.45 3,2.45, height 1.63
D0014A_N [mm] "SOIC, 14-Leads, Body 8.7x3.9mm, Pitch 1.27mm, IPC Medium Density"
  oval 1.45x0.6 smd: 1(-2.725,3.81) 2(-2.725,2.54) 3(-2.725,1.27) 4(-2.725,0) 5(-2.725,-1.27) 6(-2.725,-2.54) 7(-2.725,-3.81) 8(2.725,-3.81) 9(2.725,-2.54) 10(2.725,-1.27) 11(2.725,0) 12(2.725,1.27) 13(2.725,2.54) 14(2.725,3.81)
  silkscreen extent -3.3,-4.4 0.9,4.4, body extent -3.02,-4.32 3.02,4.32, height 1.6
DBZ0003A_N [mm] "SOT23, 3-Leads, Body 2.9x1.3mm, Pitch 0.95mm, Lead Span 2.4mm, IPC Medium Density"
  rrect17% 1x0.6 smd: 1(-1.2,0.95) 2(-1.2,-0.95) 3(1.2,0)
  silkscreen extent -1.65,-1.5 0.7,1.5, body extent -1.26,-1.46 1.26,1.46, height 0.98
DCK0006A_N [mm] "SOT23, 6-Leads, Body 2x1.3mm, Pitch 0.65mm, Lead Span 2.1mm, IPC Medium Density"
  rrect25% 0.85x0.4 smd: 1(-1.125,0.65) 2(-1.125,0) 3(-1.125,-0.65) 4(1.125,-0.65) 5(1.125,0) 6(1.125,0.65)
  silkscreen extent -1.5,-1.09 0.51,1.09, body extent -1.14,-1 1.14,1, height 0.95
DIP-4 [mm] "DIP, 4-Leads, Body 6.86x4.83mm, Pitch 2.54mm"
  rect 1.15x1.15 hole 0.65: 1(-3.81,1.27)
  round 1.15 hole 0.65: 2(-3.81,-1.27) 3(3.81,-1.27) 4(3.81,1.27)
  silkscreen extent -4,-2.41 3.43,2.52, body extent -4.02,-2.41 4.02,2.41, height 5.59
DO-201AD [mm] "Vishay dimensions"
  rect 2.1x2.1 hole 1.6: 1(-7.62,0)
  round 2.1 hole 1.6: 2(10.16,0)
  silkscreen extent -7.47,-2.7 7.57,2.61, body extent -10.82,-2.74 10.82,2.61, height 5.33
FUSE_372 [mm] "LITTELFUSE"
  round 1.5 hole 1: 1(-2.54,0) 2(2.54,0)
  silkscreen extent -4.25,-4.25 4.25,4.25, body extent -4.25,-4.25 4.25,4.25, height 8
GBU [mm] "Comchip / Diodes Inc diode bridge"
  round 2 hole 1.5: 1(-7.62,0) 2(-2.54,0) 3(2.54,0) 4(7.62,0)
  silkscreen extent -11.15,-2.28 11.15,1.28, body extent -11.15,-2.28 11.15,1.28, height 21.55
IND_7447020 [mm] "WURTH ELEKTRONIK"
  round 1.25 hole 0.75: 1(-3.5,0) 2(3.5,0)
  silkscreen extent -3.8,-7.9 3.8,7.9, body extent -3.8,-7.84 3.75,7.9, height 15.78
IND_WE-CMB_L [mm] "Wurth"
  round 2.3 hole 1.321: 2(-5,6) 4(5,6) 7(5,-6) 9(-5,-6)
  silkscreen extent -13.75,-9.25 13.75,9.25, body extent -13.75,-9.25 13.75,9.25, height 33.02
Keystone5000 [mil] "For Keystone 500x miniature loop terminals"
  round 80 hole 40: 1(0,0)
  silkscreen extent -58,-58 58,58, body extent -49,-49 49,49, height 182
Keystone5001 [mil] "For Keystone 500x miniature loop terminals"
  round 80 hole 40: 1(0,0)
  silkscreen extent -58,-58 58,58, body extent -49,-49 49,49, height 182
MF03A_N [mm] "SOT23, 3-Leads, Body 2.9x1.3mm, Pitch 0.95mm, Lead Span 2.4mm, IPC Medium Density"
  rect 1.3x0.6 smd: 1(-1.05,0.95) 2(-1.05,-0.95) 3(1.05,0)
  silkscreen extent -1.17,-1.5 0.7,1.93, body extent -0.7,-1.5 0.7,1.5, height 1.12
MPK_1800x650 [mm] "TH, 2-Leads, Body 18x6.5mm, Lead Spacing 15mm"
  round 1.35 hole 0.85: 1(-7.5,0) 2(7.5,0)
  silkscreen extent -9,-3.25 9,3.25, body extent -9,-3.25 9,3.25, height 12
MPK_1800x950 [mm] "TH, 2-Leads, Body 18x9.5mm, Lead Spacing 15mm"
  round 1.55 hole 1.05: 1(-7.5,0) 2(7.5,0)
  silkscreen extent -9,-4.75 9,4.75, body extent -9,-4.75 9,4.75, height 14
PhoenixContact_1715721 [mm] "Phoenix Contact 1715721 used on LM3445 design from Longmont"
  rrect5% 1.905x1.905 hole 1.3: 1(-2.54,0)
  round 1.9 hole 1.3: 2(2.54,0)
  silkscreen extent -5.82,-5.25 5.08,5.2, body extent -5.82,-4.6 5.08,5.2, height 14.2
S237 [mm] "EPCOS"
  round 1.75 hole 1.1: 1(-3.75,0) 2(3.75,0)
  silkscreen extent -7.5,-3.5 7.5,3.5, body extent -7.47,-3.5 7.47,3.5, height 21.99
SLPX_A5 [mm] "TH, 2-Leads, Dia 22mm, Pitch 10mm"
  rect 2.5x2.5 hole 2: 1(-5,0)
  round 2.5 hole 2: 2(5,0)
  silkscreen extent -11.7,-11.7 11.7,11.7, body extent -11.5,-11.5 11.51,11.5, height 37.01
SMA [mm] "Molded Diode, 2-Leads, Body 4.3x2.6mm, IPC Medium Density, based on OnSemi component dimensions and land pattern"
  rect 2x2 smd: 1(-2,0) 2(2,0)
  silkscreen extent -3.66,-1.57 2.79,1.57, body extent -2.6,-1.3 2.6,1.3, height 2.42
SOD-123 [mm] "On Semi recommended land pattern"
  rect 0.915x1.22 smd: 1(-1.637,0) 2(1.637,0)
  silkscreen extent -2.74,-1.17 2.03,1.17, body extent -1.93,-0.9 1.93,0.9, height 1.35
sod-323 [mm] "NXP recommended land pattern"
  rect 0.6x0.6 smd paste-0.05: 1(-1.1,0) 2(1.1,0)
  silkscreen extent -2.06,-0.86 1.53,0.86, body extent -1.3,-0.67 1.3,0.68, height 1.1
SOD-323 [mm] "NXP recommended land pattern"
  rect 0.6x0.6 smd paste-0.05: 1(-1.1,0) 2(1.1,0)
  silkscreen extent -2.06,-0.86 1.53,0.86, body extent -1.3,-0.67 1.3,0.68, height 1.1
SOT-23 [mm] "SOT23, 3-Leads, Body 2.9x1.3mm, Pitch 0.95mm, Lead Span 2.5mm, IPC Medium Density"
  rrect50% 1x0.6 smd: 1(-1.2,0.95) 2(-1.2,-0.95) 3(1.2,0)
  silkscreen extent -1.63,-1.5 0.7,1.5, body extent -1.16,-1.45 1.21,1.45, height 1
SOT-323 [mm] "Diodes Inc recommended land pattern.  2016-02-24"
  rrect21% 0.6x0.47 smd: 1(-0.95,0.65) 2(-0.95,-0.65) 3(0.95,0)
  silkscreen extent -1.14,-1.22 0.77,1.22, body extent -1.13,-1.13 1.12,1.12, height 1.13
SRN6045TA [mm] "SMD, 2-Leads, Body 6x6mm"
  rect 2.35x5.1 smd: 1(-2.075,0) 2(2.075,0)
  silkscreen extent -2.49,-3.01 2.5,2.98, body extent -3,-3 3,2.99, height 4
TDK_PFC3125ER [mm] "TH, 6-Leads, Body 26x33mm"
  rrect50% 4x4 hole 1.6: 1(-10.5,13)
  round 4 hole 1.6: 3(-10.5,0) 5(-10.5,-13) 6(10.5,-13) 7(10.5,-3.5) 8(10.5,13)
  silkscreen extent -13.6,-16.5 13,16.5, body extent -13,-16.5 13,16.5, height 27
TE_1-1318301-3 [mm] "TE"
  rect 2.9x2.9 hole 2.15: 1(-7.925,0)
  round 2.9 hole 2.15: 2(0,0) 3(7.925,0)
  silkscreen extent -10.13,-4.53 10.08,4.46, body extent -9.87,-4.28 9.87,4.22, height 10.72
TO-220AB [mil] "Copied from Altium's version of TO3B"
  rrect25% 76x118.11 hole 50: 1(-100,0)
  oval 76x118.11 hole 50: 2(0,-150) 3(100,0)
  silkscreen extent -221,-59 221,126, body extent -221,-59 221,126, height 765
TO-220AB_100mil [mm] "High Voltage staggered pins"
  rrect50% 1.8x1.8 hole 1.3: 1(-2.54,0)
  round 1.8 hole 1.3: 2(0,-2.54) 3(2.54,0)
  silkscreen extent -5.77,-1.62 5.44,3.07, body extent -5.77,-2.84 5.53,3.07, height 21.61
TO-220AC [mm]
  rrect50% 1.9x1.9 hole 1.4: 1(-2.54,0)
  round 1.9 hole 1.4: 3(2.54,0)
  silkscreen extent -5.25,-1.64 5.26,3.01, body extent -5.25,-1.64 5.26,3.01, height 19.09
VAR_S10K275E2 [mm] "EPCOS"
  round 1.6 hole 1.1: 1(-3.75,1.1) 2(3.75,-1.1)
  silkscreen extent -6,-2.7 6,2.7, body extent -5.98,-2.7 5.98,2.7, height 14.99
WCAP-FTXX_P15xPL4 [mm] "TH, Body 18x8mm, Pin Spacing 15mm"
  round 1.6 hole 1.1: 1(-7.5,0) 2(7.5,0)
  silkscreen extent -9.3,-4.3 9.3,4.3, body extent -9.25,-4.25 9.25,4.25, height 14.5
Wurth_EE13-7-4_5662 [mm] "EE13/7/4"
  rrect50% 1.7x1.7 hole 1.17: 1(-7.675,5.44)
  round 1.7 hole 1.17: 2(-7.675,2.72) 3(-7.675,0) 4(-7.675,-2.72) 5(-7.675,-5.44) 6(7.675,-5.25) 7(7.675,-1.75) 8(7.675,1.75) 9(7.675,5.25)
  silkscreen extent -10.38,-6.71 9.12,6.72, body extent -10.37,-6.71 9.13,6.71, height 9.41
Wurth_ERL35_5783_D125912 [mm] "ERL35"
  round 1.8 hole 1.3: 3(-18.6,5) 4(-18.6,0) 6(-18.6,-10) 7(-18.6,-15) 8(18.6,-15) 10(18.6,-5) 11(18.6,0) 13(18.6,10) 14(18.6,15)
  silkscreen extent -22.8,-18.25 22,18.25, body extent -21.75,-18.02 21.75,18, height 28.47

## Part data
C100 C108: library part DE2B3KY101KA2BM01, "CAP CER 100PF 300VAC RADIAL"
C101 C109: library part DE2B3KY101KA2BM01, "CAP CER 220PF 300VAC RADIAL"
C102: "CAP, CERM, 47 pF, 1000 V, +/- 5%, U2J, 1206"
C103 C104: "CAP, Film, 0.47 µF, 310 V, +/- 10%, TH"
C105: "CAP, Film, 0.47 µF, 450 V, +/- 5%, TH"
C106: "CAP, Film, 1 µF, 450 V, +/- 5%, TH"
C107: library part SLPX151M400A5P3, "CAP ALUM 150UF 20% 500V SNAP"
C110: "CAP, CERM, 1000pF, 50V, +/-10%, C0G/NP0, 0603"
C111: "CAP, CERM, 0.22 µF, 16 V, +/- 10%, X7R, 0603"
C112: "CAP, CERM, 1uF, 10V, +/-10%, X5R, 0603"
C113: "CAP, CERM, 18pF, 50V, +/-5%, C0G/NP0, 0603"
C114: "CAP, CERM, 0.22uF, 50V, +/-10%, X7R, 1206"
C115: "CAP, CERM, 220pF, 50V, +/-1%, C0G/NP0, 0603"
C116 C117: "CAP, CERM, 0.1uF, 16V, +/-10%, X5R, 0402"
C118: "CAP, AL, 6.8 µF, 450 V, +/- 20%, 58.5 ohm, TH"
C119: library part 200LLE10MEFC8X11.5, "CAP ALUM 220UF 25V 20% RADIAL"
C120: "CAP, CERM, 22 µF, 25 V, +/- 20%, X5R, 1210"
C121 C122 C125 C218: "CAP, CERM, 0.1uF, 25V, +/-5%, X7R, 0603"
C123 C212: "CAP, CERM, 1 µF, 50 V, +/- 10%, X7R, AEC-Q200 Grade 1, 1206"
C124: "CAP, CERM, 0.1uF, 25V, +/-10%, X5R, 0603"
C126: "CAP, CERM, 2.2uF, 10V, +/-10%, X5R, 0603"
C127: "CAP, CERM, 10 µF, 25 V, +/- 10%, X5R, 1206"
C128: "CAP, CERM, 0.1 µF, 25 V, +/- 5%, X7R, 0603"
C129: "CAP, CERM, 1 µF, 50 V, +/- 10%, X7R, 1206"
C130: "CAP, CERM, 22 µF, 16 V, +/- 20%, X5R, 1206_190"
C131: "CAP, CERM, 1000 pF, 100 V, +/- 5%, C0G/NP0, 0805"
C132: "CAP, CERM, 6800pF, 50V, +/-5%, X7R, 0603"
C200: "CAP, CERM, 1 µF, 50 V, +/- 10%, X7R, 0603"
C201 C211: "CAP, CERM, 0.1 µF, 50 V, +/- 10%, X7R, 1206"
C202 C216: library part Capacitor, "CAP, CERM, xxxF, xxV, [TempCo], xx%, [PackageReference]"
C203: "CAP, CERM, 1 µF, 25 V, +/- 10%, X7R, 1206"
C204: "CAP, AL, 330 µF, 50 V, +/- 20%, AEC-Q200 Grade 2, TH"
C205 C213: "CAP, CERM, 100pF, 50V, +/-1%, C0G/NP0, 0603"
C206 C207 C208 C209 C210: "CAP, CERM, 3.3 µF, 50 V, +/- 10%, X5R, 1210"
C214: "CAP, CERM, 100pF, 500V, +/-10%, X7R, 1808"
C215: "CAP, Film, 0.022 µF, 1250 V, +/- 5%, TH"
C217: "CAP, CERM, 2200 pF, 300 V, +/- 20%, Y5U, AEC-Q200 Grade 1, D9.5xT5mm"
C219: "CAP, CERM, 0.47uF, 25V, +/-10%, X7R, 1206"
C220: "CAP, CERM, 0.01 µF, 100 V, +/- 5%, X7R, 0603"
C221: "CAP, CERM, 100pF, 25V, +/-10%, X7R, 0603"
C222 C224: "CAP, CERM, 1uF, 16V, +/-10%, X5R, 0603"
C223: "CAP, CERM, 0.01 µF, 50 V, +/- 10%, X5R, 0603"
D100: "Diode, Switching-Bridge, 600V, 3A, TH"
D101: "Diode, Ultrafast, 600V, 8A, TH"
D102: library part GBU8J-BP, "Diode, Switching-Bridge, 420 V, 6 A, TH"
D103: library part BAT42WS-7-F, "Diode, Schottky, 30V, 0.2A, SOD-323"
D104 D107: "Diode, Ultrafast, 1000V, 1A, SMA"
D105: library part SS110-TP, "DIODE SCHOTTKY 150V 1A DO214AC"
D106: "Diode, TVS, Uni, 120 V, SMA"
D108: library part BAS316,115, "DIODE SWITCH 200V 200MA SOD323"
D109: "Diode, Schottky, 100 V, 1 A, SMA"
D110 D111: "Diode, Switching, 200V, 0.2A, SOD-123"
D200 D202: library part BAS316,115, "Diode, Ultrafast, 100V, 0.25A, SOD-323"
D201: "Diode, Ultrafast, 600 V, 1 A, SMA"
D203 D204: library part MBR10100G, "DIODE SCHOTTKY 120V 20A TO220AB"
D205: "Diode, P-N, 70V, 0.2A, SOT-323"
D206: "Diode, Zener, 12 V, 200 mW, SOD-323"
D207: "Diode, Schottky, 30V, 0.2A, SOD-323"
D208: "Diode, Ultrafast, 100V, 0.25A, SOD-323"
D209 D210: library part MMSZ5250B-7-F, "Diode, Zener, 20V, 500mW, SOD-123"
F100: "Fuse, 3.15 A, 250VAC/VDC, TH"
H200 H201: "Extruded heat sink with radial fins"
J100: "Header, 312mil, 3x1, Tin, TH"
J200: "Terminal Block, 5.08 mm, 2x1, TH"
L100: "Transformer, 230 uH, TH"
L101: library part 7447020, "Inductor, Toroid, Powdered Iron, 150 µH, 5A, TH"
L102: "Coupled inductor, 10 mH, 3 A, 0.105 ohm, TH"
L200: "Inductor, Shielded, Ferrite, 1 µH, 8 A, 0.012 ohm, AEC-Q200 Grade 1, SMD"
Q100: library part IPP50R199CP, "MOSFET N-CH 650V 8A TO220"
Q101: library part "MMBT4403, Fairchild Semiconductor", "Transistor, PNP, 40 V, 0.6 A, SOT-23"
Q102: library part "MMBT4403, Fairchild Semiconductor", "Transistor, PNP, 40V, 0.6A, SOT-23"
Q103: "MOSFET, N-CH, 60 V, 115 A, SOT-23"
Q200 Q201: library part IPP65R190CFD, "MOSFET N-CH 650V 11.4A TO220"
R100 R104: "RES, 750k ohm, 1%, 0.25W, 1206"
R101: "RES, 22 k, 5%, 0.25 W, 1206"
R102: "RES, 301k ohm, 1%, 0.25W, 1206"
R103: "RES, 3.0 ohm, 5%, 0.1W, 0603"
R105 R216: "RES, 10.0k ohm, 1%, 0.25W, 1206"
R106 R107 R108 R109 R110: "RES, 0.68, 1%, 1 W, 2512"
R111 R112 R113: "RES, 511k ohm, 1%, 0.25W, 1206"
R114 R115 R116: "RES, 560k ohm, 5%, 0.125W, 0805"
R117: "RES, 43.2k ohm, 1%, 0.1W, 0603"
R118: "RES, 10k ohm, 5%, 0.1W, 0603"
R119: "RES, 1.0k ohm, 5%, 0.1W, 0603"
R120: "RES, 10.0 k, 1%, 0.1 W, 0603"
R121: "RES, 8.66 k, 1%, 0.1 W, 0603"
R122: "RES, 0 ohm, 5%, 0.063W, 0402"
R123: "RES, 2.2Meg ohm, 5%, 0.1W, 0603"
R124: "RES, 619k ohm, 1%, 0.063W, 0402"
R125 R126: "RES, 10.0k ohm, 1%, 0.063W, 0402"
R127 R133: "RES, 499k ohm, 1%, 0.25W, 1206"
R128 R135 R145: "RES, 1.0Meg ohm, 5%, 0.25W, 1206"
R129: "RES, 0, 5%, 0.25 W, 1206"
R130 R137: "RES, 1.00 k, 1%, 0.1 W, 0603"
R131: "RES, 12 k, 5%, 0.1 W, 0603"
R132 R136: "RES, 100 ohm, 1%, 0.063W, 0402"
R134 R217: "RES, 15.0 ohm, 1%, 0.1W, 0603"
R138: "RES, 2.00 k, 1%, 0.25 W, 1206"
R139: "RES, 48.7 k, 1%, 0.1 W, 0603"
R140: "RES, 100k ohm, 1%, 0.1W, 0603"
R141: "RES, 23.7 k, 1%, 0.1 W, 0603"
R142: "RES, 16.2 k, 1%, 0.1 W, 0603"
R143: "RES, 20.5 k, 1%, 0.1 W, 0603"
R144: "RES, 2.05 k, 1%, 0.1 W, 0603"
R146: "RES, 41.2 k, 1%, 0.1 W, 0603"
R200 R208: "RES, 10.0, 1%, 0.1 W, 0603"
R201: "RES, 2.2, 5%, 0.125 W, 0805"
R202 R209 R225: "RES, 10.0k ohm, 1%, 0.1W, 0603"
R203: "RES, 1.00 ohm, 1%, 0.125W, 0805"
R204: "RES, 0.5, 1%, 2 W, 2512"
R205 R207: "RES, 51.1, 1%, 0.1 W, 0603"
R206 R211: library part Resistor, "RES, xxx ohm, x%, xW, [PackageReference]"
R210: "RES, 10.0 k, 1%, 0.25 W, 1206"
R212: "RES, 4.99k ohm, 1%, 0.25W, 1206"
R213: "RES, 1.47k ohm, 1%, 0.1W, 0603"
R214: "RES, 332, 1%, 0.1 W, 0603"
R215 R219 R226: "RES, 0 ohm, 5%, 0.1W, 0603"
R218: "RES, 33.2 k, 1%, 0.1 W, 0603"
R220: "RES, 100 ohm, 1%, 0.1W, 0603"
R221: "RES, 20.0k ohm, 1%, 0.1W, 0603"
R222: "RES, 4.12k ohm, 1%, 0.1W, 0603"
R223: "RES, 1.0Meg ohm, 5%, 0.1W, 0603"
R224: "RES, 2.0k ohm, 5%, 0.1W, 0603"
R227: "RES, 2.49k ohm, 1%, 0.1W, 0603"
R228: "RES, 51.1k ohm, 1%, 0.1W, 0603"
R229: "RES, 2.00k ohm, 1%, 0.1W, 0603"
R230: "RES, 1.00k ohm, 1%, 0.1W, 0603"
RT100: "Thermistor NTC, 2.2 ohm, 20%, 15x7mm"
RV100: "Varistor 275V RMS 10MM Radial, TH"
T100: "Transformer, 1500 uH, EE13/7/4, TH"
T200: "Transformer, 310 uH, ERL35, TH"
TP200: "Test Point, Miniature, Red, TH"
TP201: "Test Point, Miniature, Black, TH"
U100: "PFC Controller for low to medium power applications requiring compliance with IEC 61000-3-2, D0008A (SOIC-8)"
U101: "Resistor-Programmable, up to 18V-Capable Temp Switch and Analog Out Sensor, DCK0006A (SOT-6)"
U102: "Dual Comparator, D0008A"
U103: "High-Voltage Flyback Switcher with Primary-Side Regulation and Constant-Current Control, D0007A (SOIC-7)"
U104: "Precision Micropower Shunt Voltage Reference, 3-pin SOT-23"
U200: "High-Speed, 4-A, 600-V High-Side Low-Side Gate Driver, D0014A (SOIC-14)"
U201: "High-Performance Resonant Mode Controller with Voltage Control, 50 % Duty Cycle, -40 to +125 degC, 8-pin SOIC (D), Green (RoHS & no Sb/Br)"
U202 U204: library part FOD817A, "OPTOISOLATOR 5KV TRANSISTOR 4DIP"
U203: "Adjustable Precision Shunt Regulator, 34 ppm / degC, 100 mA, -40 to 85 degC, 3-pin SOT-23 (DBZ), Green (RoHS & no Sb/Br)"

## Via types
v1: diameter 20, hole 10, Top Layer to Bottom Layer, 118 vias
v2: diameter 100, hole 80, Top Layer to Bottom Layer, 3 vias

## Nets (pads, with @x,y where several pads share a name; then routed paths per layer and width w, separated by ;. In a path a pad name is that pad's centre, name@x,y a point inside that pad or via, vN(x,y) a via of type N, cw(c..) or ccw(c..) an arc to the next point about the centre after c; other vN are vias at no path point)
5V: C117.1 C131.1 Q102.2 R122.2 R126.2 R130.2 R137.2 R138.1 U104.1 | length 1448.2
  Top Layer w20: v1(4100,1740) 4126.05,1740 v1(4186.05,1800) ; v1(4160,2250) 4290,2380 4350,2380 4357.87,2387.87 4502.13,2387.87 v1(4510,2380)
  Bottom Layer w20: Q102.2@4065.35,1740 v1(4100,1740) ; R126.2@4076.38,1640 C117.1@4076.38,1690 4076.38,1733.7 ; R138.1@4130,2316.85 4130,2280 v1(4160,2250) ; C131.1@4131.5,2083.27 C131.1@4131.5,2090 ; C131.1@4137.4,2095.91 U104.1@4137.4,2158.66 4137.4,2227.4 v1(4160,2250) ; C131.1@4140,2090 4140,1846.38 4167.32,1819.06 4167.32,1818.73 v1(4186.05,1800) 4276.05,1710 R122.2@4276.38,1710 ; R130.2@4210,2238.5 4198.5,2250 v1(4160,2250) ; v1(4510,2380) 4510,2411.5 R137.2@4528.5,2430
12V: C119.1 C120.2 C121.1 C122.1 C123.1 D105.1 R212.2 R216.2 | length 2028
  Top Layer w50: D105.1@6328.74,1240 6328.74,1148.74 6294.96,1114.96 C120.2@6294.96,1080 6477.07,1080 C119.1@6502.62,1105.55
  Bottom Layer w20: R216.2@5097.09,1259.37 5117.72,1280 5237.09,1280 R212.2@5297.09,1220 5319.21,1197.87 6000.4,1197.87 6054.77,1143.5 6422.62,1143.5 C123.1@6422.62,1133.58 ; R212.2@5295.43,1190 R212.2@5297.09,1190
  Bottom Layer w50: C123.1@6422.62,1133.58 6474.59,1133.58 C119.1@6502.62,1105.55 6531.52,1076.65 C121.1@6632.62,1076.65
B+: C107.1 D100.1 D101.1 Q200.2 R113.1 R127.2 | length 4941.4
  Top Layer w20: C107.1@2280,933.15 2400,1053.15 2400,1501.01 2958.99,2060 3182.91,2060 R113.1@3212.91,2090 ; D100.1@2870,870 2870,1340 3120,1590 ; Q200.2@3120,1070 3120,1590 ; v1(4680,1930) 4650,1900 4139.21,1900 3987.8,2051.42 3871.42,2051.42 3660,1840 3370,1840 3120,1590
  Bottom Layer w20: v1(4680,1930) R127.2@4777.09,1930
BIAS: C114.1 C124.1 C128.1 C129.1 C130.1 C200.2 C218.1 D109.1 R131.2 R138.2 R201.1 R203.2 U100.8 U102.8 U201.7 | length 6972.6
  Top Layer w20: R201.1@3140,264.41 v1(3140,311.1) ; C114.1@3262.09,2315 U100.8@3352.72,2315 3457.13,2315 3462.13,2320 3462.13,2412.13 3510,2460 3510,2490 3610,2590 4120,2590 4230,2480 v1(4310,2480) 4660,2480 4763.62,2376.38 4763.62,2026.96 4802.13,1988.45 4802.13,1842.13 4730,1770 v1(4690,1770)
  Bottom Layer w20: C200.2@3101.5,260 R203.2@3170,260 3170,240 3210,200 3350,200 3475,325 U201.7@3602.72,325 3685.58,325 3708.5,347.92 C218.1@3708.5,440 3708.5,440.67 3870.9,603.07 C130.1@5370,603.07 ; 3140,261.1 v1(3140,311.1) ; R138.2@4143.15,2410 R138.2@4130,2423.15 4186.85,2480 v1(4310,2480) R131.2@4310,2431.5 ; R131.2@4311.5,2430 C124.1@4378.5,2430 C128.1@4378.5,2490 ; U102.8@4372.72,2355 C124.1@4372.72,2424.21 ; 4742.13,605.2 4742.13,1597.87 4660,1680 4660,1740 v1(4690,1770) 4742.91,1770 C129.1@4770,1797.09
  Bottom Layer w50: C130.1@5370,603.07 5478.19,603.07 D109.1@5481.26,600
CS: Q100.3 R106.2 R107.2 R108.2 R109.2 R110.2 R119.2 | length 2114.6
  Bottom Layer w20: R108.2@2327.01,2206.14 2327.01,2142.99 2360,2110 2730,2110 3070,2450 3120,2450 3197.76,2527.76 3406.73,2527.76 3436.73,2557.76 R119.2@3448.5,2557.76
  Bottom Layer w100: 1916.14,2206.14 R107.2@2007.01,2206.14 R106.2@2167.01,2206.14 R108.2@2327.01,2206.14 R110.2@2487.01,2206.14 R109.2@2647.01,2206.14
NetC100_2: C100.2 F100.2 J100.3 | length 1025
  Top Layer w50: J100.3@1007.48,2050 C100.2@1007.48,2330
  Top Layer w100: J100.3@1007.48,2050 1170,2050 F100.2@1220,2100
  Bottom Layer w50: C100.2@1007.48,2330 1007.48,2052.52 1010,2050
  Bottom Layer w100: 1010,2050 1170,2050 F100.2@1220,2100
NetC101_2: C101.2 C104.1 D102.2 L102.7 | length 2472.1
  Top Layer w50: C101.2@447.48,1440 447.48,1327.48 370,1250 370,910 470,810 860,810 976.85,693.15 L102.7@976.85,573.78
  Top Layer w100: L102.7@976.85,573.78 976.85,528.43 1235.28,270 ; C104.1@1235.28,180 1235.28,270 ; D102.2@1700,580 1545.28,580 1235.28,270
NetC102_1: C102.1 D101.3 L100.6 Q100.2 | length 1482.5
  Top Layer w20: Q100.2@1830,1920 2100,2190 v1(3080,2190)
  Top Layer w100: L100.6@2008.19,1688.19 L100.6@2008.19,1726.61 L100.6@2008.19,1741.81
  Bottom Layer w20: v1(3080,2190) C102.1@3147.09,2190
NetC102_2: C102.2 R101.2 | length 95.8
  Bottom Layer w20: C102.2@3154.17,2302.91 R101.2@3250,2302.91
NetC103_1: C103.1 F100.1 L102.4 R100.2 RV100.2 | length 2078.8
  Top Layer w100: L102.4@976.85,1046.22 976.85,1091.57 C103.1@1255.28,1370 1255.28,1609.06 RV100.2@1227.64,1636.69 1220,1644.33 F100.1@1220,1900
  Bottom Layer w25: R100.2@1167.09,1370 1220,1370 C103.1@1255.28,1370
  Bottom Layer w100: L102.4@976.85,1046.22 1066.22,1046.22 1220,1200 1220,1370 F100.1@1220,1900
NetC103_2: C103.2 L102.2 R104.1 RT100.2 | length 88.2
  Bottom Layer w25: C103.2@664.72,1370 R104.1@752.91,1370
NetC104_2: C104.2 C109.1 D102.3 L102.9 | length 2221.2
  Top Layer w50: C109.1@497.48,280 614.72,280
  Top Layer w100: L102.9@583.15,573.78 644.72,512.2 C104.2@644.72,180
  Bottom Layer w50: C109.1@497.48,280 624.72,280
  Bottom Layer w100: L102.9@583.15,573.78 644.72,512.2 C104.2@644.72,180 920,180 1120,380 D102.3@1700,380
NetC105_1: C105.1 D102.1 L101.1 | length 1089
  Top Layer w100: D102.1@1700,780 1980,780 2230,530 C105.1@2445.28,530 2542.2,433.07 L101.1@2542.2,330
NetC108_1: C108.1 J100.1 RT100.1 RV100.1 | length 529
  Top Layer w50: J100.1@312.52,2065.48 C108.1@312.52,2330
  Bottom Layer w50: J100.1@312.52,2065.48 C108.1@312.52,2330
NetC110_1: C110.1 R116.1 R120.2 U100.3 | length 657.1
  Top Layer w20: R120.2@3642.81,2477.15 3580.67,2415 U100.3@3567.28,2415 3505,2415 3490,2400 3490,2290 3500,2280 3561.49,2280 3593.62,2247.87 3593.62,2146.38 R116.1@3650,2090 ; R120.2@3648.5,2471.46 C110.1@3648.5,2531.46
NetC111_1: C111.1 R118.1 | length 88.4
  Bottom Layer w12: C111.1@3658.5,2425.67 3660.04,2425.67 R118.1@3721.5,2364.21
NetC112_1: C112.1 R118.2 U100.2 | length 152.3
  Top Layer w20: U100.2@3567.28,2365 3615,2365 v1(3620,2360) 3620,2382.95 C112.1@3648.5,2411.46
  Bottom Layer w20: v1(3620,2360) R118.2@3654.29,2360
NetC115_1: C115.1 R119.1 U100.4 | length 136.1
  Top Layer w20: U100.4@3557.48,2465 U100.4@3567.28,2465 ; U100.4@3570,2467.72 v1(3570,2498.27)
  Bottom Layer w20: 3511.5,2520 R119.1@3511.5,2557.76 ; C115.1@3512.01,2498.27 v1(3570,2498.27)
NetC116_1: C116.1 R122.1 U101.4 U101.6 | length 229
  Bottom Layer w12: R122.1@4323.62,1710 C116.1@4323.62,1660 4344.29,1639.33 U101.4@4344.29,1605.59 4374.41,1605.59 4380,1600 4380,1560 4374.41,1554.41 U101.6@4344.29,1554.41
NetC117_2: C117.2 Q102.1 R125.1 R126.1 | length 181.2
  Bottom Layer w12: Q102.1@4137.4,1742.76 4137.4,1703.78 C117.2@4123.62,1690 R126.1@4123.62,1640 R125.1@4196.38,1640
NetC118_1: C118.1 D104.1 D106.2 T100.5 | length 1414.6
  Top Layer w50: D104.1@5070,468.74 5350.31,468.74 C118.1@5370,488.43 5370,530 5490,650 5980,650 6074.17,555.83 T100.5@6074.17,487.83
  Bottom Layer w50: T100.5@6074.17,487.83 6245.07,487.83 D106.2@6268.5,511.26
NetC125_1: C125.1 Q103.1 R132.1 R136.2 R140.2 | length 236.6
  Bottom Layer w20: R140.2@3901.5,2340 R140.2@3907.4,2340 ; C125.1@3907.4,2285.91 R140.2@3907.4,2340 ; Q103.1@3907.4,2402.76 R140.2@3907.4,2340 ; C125.1@3911.5,2290 R132.1@3966.38,2290 ; R136.2@3966.38,2340 R140.2@3907.4,2340
NetC126_1: C126.1 R135.1 R141.2 R145.2 U102.5 | length 300.2
  Bottom Layer w20: U102.5@4383.5,2205 U102.5@4372.72,2205 4372.72,2140 C126.1@4448.5,2140 R141.2@4448.5,2070 ; R135.1@4448.5,2001.42 R141.2@4448.5,2080
NetC127_2: C127.2 D108.1 U103.6 | length 313.6
  Top Layer w20: C127.2@5886.93,100 5880,106.93 5880,220 5895,235 U103.6@5927.28,235 5975,235 v1(5980,240)
  Bottom Layer w20: D108.1@5923.31,280 5955.67,280 5980,255.67 v1(5980,240)
NetC132_1: C132.1 R133.1 R142.2 R146.1 U102.3 | length 437.2
  Bottom Layer w20: U102.3@4587.28,2255 4660,2255 ; R142.2@4661.5,2080 C132.1@4661.5,2140 4661.5,2253.5 4660,2255 ; R146.1@4678.5,2320 4678.5,2256.5 4680,2255 ; R133.1@4780,2247.09 4772.09,2255 4680,2255 ; 4660,2255 4680,2255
